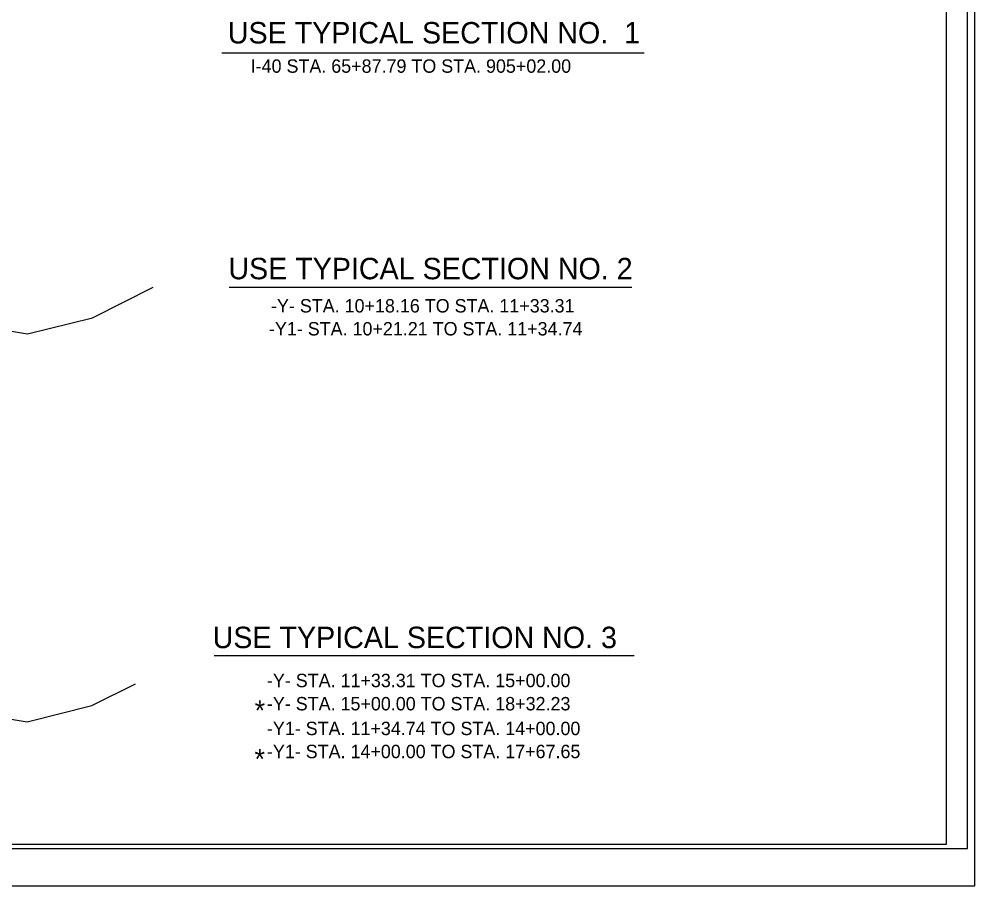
# Model space of a CAD drawing. Extents: x 2137858 to 2138172, y 2136084 to 2136289.
# Drawn here: x 2138065.4 to 2138172.5, y 2136083.7 to 2136180.7 of the extents above; entities that cross this region are included whole.
import ezdxf

# ---------------------------------------------------------------- set-up
doc = ezdxf.new("R2010")
doc.units = 0
for name, color, linetype in [('Old_Level_1', 7, 'Continuous'), ('Old_Level_3', 7, 'Continuous'), ('Sheet Cutting Line CELL', 7, 'Continuous'), ('Sheet Plot Border Inside CELL', 7, 'Continuous'), ('Sheet Plot Border Outside CELL', 7, 'Continuous'), ('Sheet Typical CELL', 7, 'Continuous')]:
    doc.layers.add(name, color=color, linetype=linetype)

msp = doc.modelspace()

# ---------------------------------------------------------------- linework, layer by layer
at = {"layer": 'Old_Level_1'}
for p, q in [((2138088.11, 2136176.94), (2138135.44, 2136176.94)), ((2138073.61, 2136147.29), (2138080.42, 2136150.7)), ((2138088.94, 2136150.7), (2138134.03, 2136150.7)), ((2138044.57, 2136149.11), (2138066.35, 2136145.48)), ((2138066.35, 2136145.48), (2138073.61, 2136147.29)), ((2138087.25, 2136109.48), (2138134.3, 2136109.48)), ((2138073.54, 2136103.85), (2138078.43, 2136106.29)), ((2138044.5, 2136105.66), (2138066.28, 2136102.03)), ((2138066.28, 2136102.03), (2138073.54, 2136103.85))]:
    msp.add_line(p, q, dxfattribs=at)
at = {"layer": 'Sheet Cutting Line CELL'}
msp.add_line((2137858.14, 2136083.67), (2138172.48, 2136083.67), dxfattribs=at)
at = {"layer": 'Sheet Plot Border Inside CELL'}
msp.add_lwpolyline([(2138171.64, 2136284.82), (2137860.56, 2136284.82), (2137860.56, 2136087.86), (2138171.64, 2136087.86)], close=True, dxfattribs=at)
at = {"layer": 'Sheet Plot Border Outside CELL'}
msp.add_lwpolyline([(2138172.48, 2136289.01), (2137858.14, 2136289.01), (2137858.14, 2136083.67), (2138172.48, 2136083.67)], close=True, dxfattribs=at)
at = {"layer": 'Sheet Typical CELL'}
msp.add_lwpolyline([(2138169.31, 2136284.34), (2137889.31, 2136284.34), (2137889.31, 2136088.34), (2138169.31, 2136088.34)], close=True, dxfattribs=at)

# ---------------------------------------------------------------- texts
at = {"layer": 'Old_Level_1'}
for s, height, p in [('I-40 STA. 65+87.79 TO STA. 905+02.00', 1.5, (2138091.34, 2136174.71)), ('-Y- STA. 10+18.16 TO STA. 11+33.31', 1.5, (2138093.62, 2136147.87)), ('-Y1- STA. 10+21.21 TO STA. 11+34.74', 1.5, (2138093.39, 2136145.3)), ('-Y- STA. 11+33.31 TO STA. 15+00.00', 1.5, (2138093.16, 2136105.92)), ('-Y- STA. 15+00.00 TO STA. 18+32.23', 1.5, (2138093.16, 2136103.32)), ('*', 2.25, (2138091.79, 2136102.19)), ('-Y1- STA. 11+34.74 TO STA. 14+00.00', 1.5, (2138093.16, 2136100.55)), ('-Y1- STA. 14+00.00 TO STA. 17+67.65', 1.5, (2138093.16, 2136097.97)), ('*', 2.25, (2138091.77, 2136096.76))]:
    msp.add_text(s, height=height, dxfattribs=at).set_placement(p)
at = {"layer": 'Old_Level_3'}
for s, p in [('USE TYPICAL SECTION NO.  1', (2138088.78, 2136177.99)), ('USE TYPICAL SECTION NO. 2', (2138088.84, 2136151.59)), ('USE TYPICAL SECTION NO. 3  ', (2138087.08, 2136110.29))]:
    msp.add_text(s, height=2.4, dxfattribs=at).set_placement(p)

doc.saveas('drawing.dxf')
